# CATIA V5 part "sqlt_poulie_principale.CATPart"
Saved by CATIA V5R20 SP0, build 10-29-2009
Part number: sqlt_poulie_principale
Publications: "rayon_poulie", "largeur_rainure", "profondeur_rainure", "hauteur_poulie", "Plan.1", "Point.1", "Droite.1", "Point.2", "Point.3", "Plan.2", "Point.4", "Point.5", "Point.6", "Point.7", "Point.8"
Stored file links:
  D:\ecole\thinkmotion\sqlt_poulie_principale.CATPart
  D:\ecole\thinkmotion\sqlt_eolienne.CATProduct
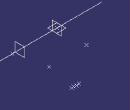
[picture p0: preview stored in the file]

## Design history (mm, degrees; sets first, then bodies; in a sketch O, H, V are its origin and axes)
Parameters
  rayon_poulie = 80 mm {= External.rayon_poulie_principale}
  largeur_rainure = 3 mm {= External.largeur_rainure_poulie_principale}
  profondeur_rainure = 1 mm {= External.profondeur_rainure_poulie_principale}
  hauteur_poulie = 10 mm {= External.hauteur_poulie_principale}
External parameters (linked from other documents)
  External.rayon_trou = 40 mm
  External.rayon_poulie_principale = 80 mm
  External.largeur_rainure_poulie_principale = 3 mm
  External.profondeur_rainure_poulie_principale = 1 mm
  External.hauteur_poulie_principale = 10 mm
Set1 "sqlt_poulie_pricipale"
  Plane1: type OffsetPt, RefPlane xy-plane, RefPoint Point1
  Point1: (0, 0, 0)
  Line1: type PtDir, RefPoint Point1, Direction yz-plane, Start 0, End 20
  Point2: (0, 40 {= External.rayon_trou}, 0)
  Point3: (50 {= 50mm}, 40 {= External.rayon_trou}, 0)
  Plane2: type Offset, RefPlane yz-plane, Offset 50
  Point4: (50, 80 {= rayon_poulie}, 0)
  Point5: (60 {= 50mm+hauteur_poulie}, 80 {= rayon_poulie}, 0)
  Point6: (60 {= 50mm+hauteur_poulie}, 0, 0)
  Point7: (53.5 {= 50mm+(hauteur_poulie -largeur_rainure )/2}, 80 {= rayon_poulie}, 0)
  Point8: (56.5 {= 50mm+(hauteur_poulie -largeur_rainure )/2+largeur_rainure}, 79 {= rayon_poulie -profondeur_rainure}, 0)
  Plane3: type Offset, RefPlane yz-plane, Offset 0
Body1 (main body)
